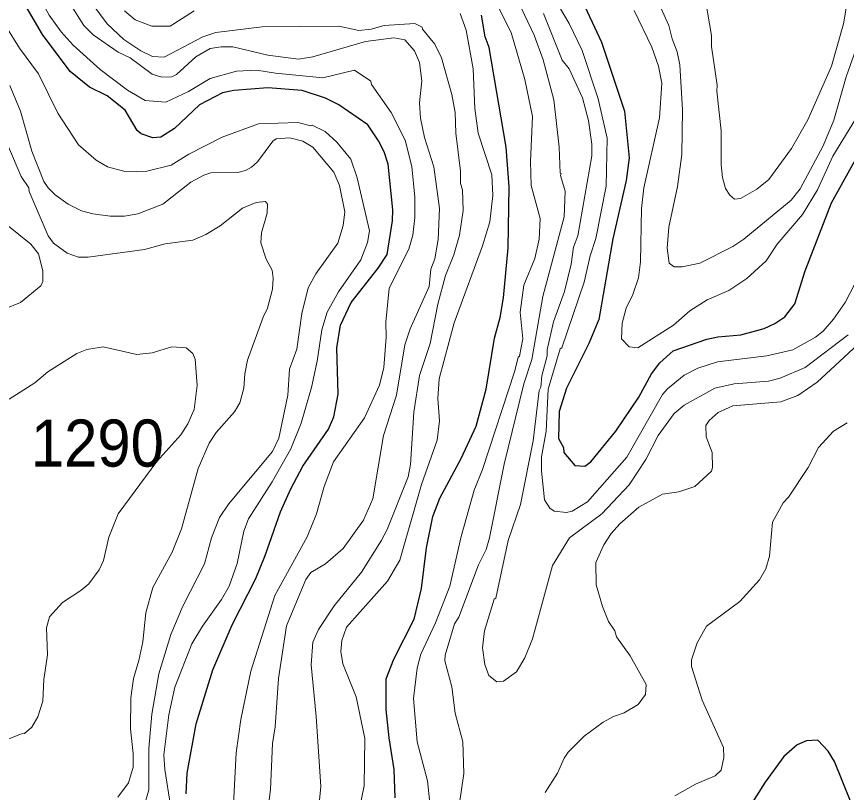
# Model space of a CAD drawing. Extents: x 598.3 to 623.2, y 6902.2 to 6930.1.
# Drawn here: x 605.43 to 606.84, y 6922.266 to 6923.585 of the extents above; entities that cross this region are included whole.
import ezdxf

# ---------------------------------------------------------------- set-up
doc = ezdxf.new("R2010")
doc.units = 0
doc.header["$LTSCALE"] = 0.032
doc.layers.add('1', color=7, linetype='Continuous', lineweight=25)
doc.layers.add('2', color=7, linetype='Continuous', lineweight=13)
doc.layers.add('21', color=7, linetype='Continuous')

msp = doc.modelspace()

# ---------------------------------------------------------------- linework, layer by layer
at = {"layer": '1'}
for points in [[(606.3883, 6923.6191), (606.4241, 6923.541), (606.4632, 6923.4239), (606.4712, 6923.3445), (606.4663, 6923.306), (606.4437, 6923.2072), (606.4195, 6923.0699), (606.4026, 6923.0294), (606.3646, 6922.9533), (606.3522, 6922.9139), (606.3514, 6922.8675), (606.3595, 6922.8526), (606.3604, 6922.8439), (606.379, 6922.8221), (606.3957, 6922.8207), (606.4062, 6922.8283), (606.4485, 6922.8802), (606.4878, 6922.9379), (606.5094, 6922.9776), (606.5237, 6922.9965), (606.5463, 6923.0169), (606.6031, 6923.0366), (606.6221, 6923.0405), (606.6609, 6923.0438), (606.7008, 6923.0549), (606.7187, 6923.063), (606.7358, 6923.0745), (606.7529, 6923.0964), (606.7702, 6923.1529), (606.8149, 6923.2681), (606.8912, 6923.4045)], [(605.7184, 6922.264), (605.72, 6922.299), (605.7354, 6922.3827), (605.764, 6922.4745), (605.7966, 6922.5509), (605.8369, 6922.6299), (605.853, 6922.6688), (605.879, 6922.7429), (605.8962, 6922.7824), (605.9167, 6922.8207), (605.9604, 6922.8836), (605.9694, 6922.9048), (605.9766, 6922.943), (605.9743, 6923.0217), (605.9807, 6923.0602), (605.9987, 6923.099), (606.0446, 6923.157), (606.06, 6923.1805), (606.0689, 6923.2377), (606.0697, 6923.2561), (606.0618, 6923.3338), (606.055, 6923.3548), (606.0456, 6923.3738), (606.0274, 6923.4008), (605.9777, 6923.4345), (605.9551, 6923.4459), (605.9159, 6923.4589), (605.8573, 6923.4638), (605.7996, 6923.459), (605.7802, 6923.455), (605.7414, 6923.4349), (605.6987, 6923.3947), (605.6752, 6923.3799), (605.6617, 6923.3789), (605.6422, 6923.3855), (605.6353, 6923.3909), (605.6148, 6923.4258), (605.5843, 6923.45), (605.5543, 6923.465), (605.5211, 6923.4911), (605.4746, 6923.5542), (605.4373, 6923.6175)], [(606.0738, 6922.257), (606.0722, 6922.3051), (606.0632, 6922.3592), (606.0585, 6922.4071), (606.0585, 6922.4592), (606.0712, 6922.493), (606.1057, 6922.5609), (606.1183, 6922.6127), (606.1268, 6922.6817), (606.1377, 6922.7352), (606.1497, 6922.7666), (606.1857, 6922.8335), (606.2112, 6922.8888), (606.2285, 6922.9517), (606.2425, 6923.0383), (606.2519, 6923.0731), (606.2575, 6923.1065), (606.2656, 6923.192), (606.2672, 6923.2953), (606.2623, 6923.3629), (606.2333, 6923.5323), (606.2268, 6923.5501), (606.2201, 6923.5868)], [(606.8614, 6922.2164), (606.82, 6922.3187), (606.8096, 6922.3362), (606.7922, 6922.3553), (606.7724, 6922.354), (606.7569, 6922.347), (606.7342, 6922.3272), (606.7027, 6922.2837), (606.6772, 6922.2433)]]:
    msp.add_lwpolyline(points, dxfattribs=at)
at = {"layer": '2'}
for points in [[(605.4267, 6923.7275), (605.4576, 6923.6398), (605.4858, 6923.5868), (605.5059, 6923.559), (605.5263, 6923.536), (605.5725, 6923.4947), (605.6186, 6923.4595), (605.6488, 6923.4421), (605.6842, 6923.4395), (605.7222, 6923.4576), (605.7591, 6923.4793)], [(606.5969, 6923.6357), (606.6112, 6923.5524), (606.6114, 6923.5339), (606.6209, 6923.4679), (606.6202, 6923.458), (606.6274, 6923.3908), (606.6274, 6923.3326)], [(605.8504, 6922.1827), (605.8618, 6922.2713), (605.8653, 6922.3497), (605.8697, 6922.3778), (605.8753, 6922.46), (605.8891, 6922.5494), (605.922, 6922.6279), (605.9306, 6922.6398), (605.9552, 6922.6548), (605.9852, 6922.6806), (606.02, 6922.7289), (606.0357, 6922.7653), (606.0541, 6922.8728), (606.0761, 6922.9412), (606.0901, 6923.0269), (606.0992, 6923.0543), (606.1312, 6923.1263), (606.1345, 6923.1554), (606.1409, 6923.1733), (606.1467, 6923.2059), (606.1491, 6923.2586), (606.1396, 6923.3294), (606.1238, 6923.3794), (606.1167, 6923.4123), (606.1151, 6923.4381), (606.1192, 6923.4756), (606.115, 6923.5067), (606.1068, 6923.5263), (606.0902, 6923.5449), (606.0713, 6923.5488), (606.0231, 6923.5424), (605.934, 6923.5165), (605.9094, 6923.5125), (605.8575, 6923.5193), (605.7977, 6923.5334), (605.7778, 6923.5334), (605.7592, 6923.5303), (605.7347, 6923.5164), (605.702, 6923.4863), (605.6939, 6923.4824), (605.6774, 6923.4817), (605.6607, 6923.487), (605.6232, 6923.5147), (605.6031, 6923.5242), (605.5603, 6923.5538), (605.5446, 6923.5696), (605.5133, 6923.6191)], [(605.5466, 6923.6236), (605.584, 6923.5723), (605.6128, 6923.546), (605.6414, 6923.5267), (605.6612, 6923.5167), (605.6809, 6923.5156), (605.747, 6923.5502), (605.7687, 6923.5577), (605.8477, 6923.5674), (605.9779, 6923.5682), (606.012, 6923.561), (606.0328, 6923.5634), (606.0552, 6923.5698), (606.1069, 6923.5731), (606.1198, 6923.5666), (606.1201, 6923.5634), (606.1408, 6923.5378), (606.1523, 6923.5146), (606.1701, 6923.452), (606.1757, 6923.4215), (606.1766, 6923.3863), (606.1846, 6923.3222), (606.1847, 6923.3012), (606.1879, 6923.2903), (606.1895, 6923.2552), (606.1829, 6923.2132), (606.1734, 6923.18), (606.1592, 6923.1447), (606.1459, 6923.0958), (606.1329, 6923.0294), (606.1148, 6922.9748), (606.1053, 6922.9123), (606.0997, 6922.8238), (606.0957, 6922.8028), (606.0598, 6922.7129), (606.0501, 6922.6938), (606.0165, 6922.6409), (605.97, 6922.5834), (605.9433, 6922.5432), (605.934, 6922.5214), (605.9307, 6922.4831), (605.9395, 6922.3955), (605.9475, 6922.2766), (605.9426, 6922.2308)], [(606.1903, 6922.2985), (606.1887, 6922.3524), (606.1758, 6922.4008), (606.1702, 6922.4458), (606.158, 6922.4898), (606.1587, 6922.4995), (606.1747, 6922.5526), (606.1818, 6922.5639), (606.2152, 6922.653), (606.2283, 6922.6794), (606.2341, 6922.6992), (606.2589, 6922.8242), (606.2925, 6922.9605), (606.3061, 6923.0019), (606.3248, 6923.1088), (606.3611, 6923.2445), (606.3627, 6923.2881), (606.3548, 6923.3144), (606.356, 6923.318), (606.3539, 6923.3185), (606.3524, 6923.3628), (606.3434, 6923.4431), (606.3249, 6923.5111), (606.3097, 6923.5529), (606.2784, 6923.6203)], [(606.5577, 6923.5025), (606.553, 6923.5245), (606.5442, 6923.5466), (606.5385, 6923.5696), (606.5116, 6923.6301)], [(606.6274, 6923.3326), (606.6298, 6923.3111), (606.6349, 6923.2928), (606.6424, 6923.2813), (606.6505, 6923.2745), (606.6606, 6923.2753), (606.6884, 6923.2916), (606.7086, 6923.3078), (606.7471, 6923.3608), (606.7747, 6923.4094), (606.8153, 6923.5005), (606.8354, 6923.5726), (606.8436, 6923.62)], [(606.2415, 6923.6166), (606.271, 6923.5575), (606.2939, 6923.4776), (606.3069, 6923.415), (606.3036, 6923.3383), (606.3045, 6923.2977), (606.3198, 6923.2415), (606.3182, 6923.2066), (606.3111, 6923.1738), (606.2925, 6923.1285), (606.2859, 6923.0823), (606.2907, 6923.037), (606.285, 6923.0077), (606.2825, 6923.0061), (606.2771, 6922.9828), (606.2223, 6922.8148), (606.2081, 6922.7798), (606.1856, 6922.7015), (606.1665, 6922.6169), (606.1424, 6922.5546), (606.1173, 6922.5014), (606.1111, 6922.4777), (606.1046, 6922.4262), (606.111, 6922.3524), (606.1288, 6922.2863), (606.1344, 6922.2321)], [(606.3337, 6922.9513), (606.3538, 6923.02), (606.3571, 6923.0216), (606.3948, 6923.1334), (606.4049, 6923.1784), (606.4146, 6923.2075), (606.4323, 6923.2963), (606.4339, 6923.3778), (606.4187, 6923.445), (606.3915, 6923.5268), (606.3694, 6923.5729), (606.3456, 6923.6138)], [(605.7323, 6923.5946), (605.6915, 6923.5685), (605.6604, 6923.5682), (605.6317, 6923.579), (605.6135, 6923.5945)], [(606.48, 6923.5952), (606.5099, 6923.5329), (606.5214, 6923.5005), (606.527, 6923.4714), (606.523, 6923.4128), (606.4962, 6923.2937), (606.4923, 6923.2583), (606.4906, 6923.1679), (606.4869, 6923.1407), (606.4774, 6923.1125), (606.4664, 6923.0893), (606.4597, 6923.0638), (606.4581, 6923.0369), (606.4714, 6923.0235), (606.4858, 6923.0219), (606.5469, 6923.0603), (606.5746, 6923.0847), (606.6038, 6923.1035), (606.6405, 6923.1194), (606.6714, 6923.1397), (606.7039, 6923.1696), (606.7231, 6923.1977), (606.7659, 6923.2486), (606.7912, 6923.2904), (606.8174, 6923.3476), (606.862, 6923.4204)], [(606.0064, 6922.2061), (606.0211, 6922.2777), (606.0219, 6922.3578), (606.0074, 6922.4288), (605.9848, 6922.4849), (605.9816, 6922.5057), (605.9829, 6922.5247), (605.9907, 6922.5472), (606.0604, 6922.6255), (606.0814, 6922.661), (606.1183, 6922.7898), (606.1449, 6922.8651), (606.149, 6922.8975), (606.1459, 6922.9359), (606.1482, 6922.969), (606.1741, 6923.0645), (606.2223, 6923.1953), (606.2347, 6923.2358), (606.2397, 6923.2806), (606.2381, 6923.316), (606.2147, 6923.3864), (606.2091, 6923.4285), (606.2065, 6923.4957), (606.1944, 6923.5616), (606.1839, 6923.5899)], [(606.3259, 6923.59), (606.3574, 6923.5108), (606.3691, 6923.4957), (606.392, 6923.4466), (606.4024, 6923.408), (606.408, 6923.3678), (606.408, 6923.3479), (606.3839, 6923.2124), (606.3766, 6923.1929), (606.3725, 6923.1638), (606.3617, 6923.1173), (606.3425, 6923.0662), (606.3322, 6923.0184), (606.332, 6923.0081), (606.3231, 6922.9744), (606.3214, 6922.9549), (606.3182, 6922.9495), (606.308, 6922.8639), (606.2867, 6922.7558), (606.2657, 6922.6943), (606.2447, 6922.5967), (606.242, 6922.5945), (606.2257, 6922.5409), (606.222, 6922.5118), (606.2259, 6922.4835), (606.2331, 6922.4652), (606.2463, 6922.4545), (606.2577, 6922.4553), (606.2799, 6922.4714), (606.2939, 6922.4949), (606.307, 6922.5275), (606.341, 6922.6521), (606.37, 6922.6988), (606.4251, 6922.7398), (606.4716, 6922.7888), (606.4998, 6922.8322)], [(605.6821, 6922.3054), (605.6804, 6922.3303), (605.689, 6922.3984), (605.699, 6922.445), (605.7281, 6922.519), (605.7463, 6922.5489), (605.7785, 6922.5939), (605.7915, 6922.6169), (605.8051, 6922.6554), (605.8164, 6922.7105), (605.8244, 6922.7313), (605.8649, 6922.7944), (605.8961, 6922.8504), (605.914, 6922.8937), (605.9313, 6922.9544), (605.9409, 6922.9994), (605.9489, 6923.0525), (605.9579, 6923.0823), (605.9776, 6923.1168), (606.0154, 6923.1714), (606.0269, 6923.201), (606.0299, 6923.2208), (606.009, 6923.3108), (605.9981, 6923.3422), (605.9746, 6923.3712), (605.9547, 6923.3893), (605.9324, 6923.4004), (605.9301, 6923.3992), (605.9084, 6923.4047), (605.8415, 6923.4023), (605.7799, 6923.3796), (605.7228, 6923.351), (605.6931, 6923.3321), (605.6517, 6923.3221), (605.6163, 6923.3207), (605.5846, 6923.3292), (605.5656, 6923.3409), (605.5357, 6923.3665), (605.5002, 6923.4208), (605.4675, 6923.4875), (605.4352, 6923.5308), (605.4119, 6923.5686)], [(606.86, 6923.5381), (606.8403, 6923.4824), (606.819, 6923.4086), (606.8012, 6923.3653), (606.762, 6923.292), (606.7466, 6923.2729), (606.6664, 6923.2062), (606.6475, 6923.1941), (606.5916, 6923.1654), (606.5612, 6923.1597), (606.5477, 6923.1595), (606.5391, 6923.1656), (606.5361, 6923.1911), (606.5389, 6923.2266), (606.5532, 6923.2957), (606.561, 6923.3502), (606.5619, 6923.4265), (606.5577, 6923.5025)], [(605.7591, 6923.4793), (605.804, 6923.4921), (605.8385, 6923.4937), (605.8705, 6923.4883), (605.9509, 6923.4808), (606.0043, 6923.4936), (606.0324, 6923.475), (606.0334, 6923.4695), (606.0666, 6923.4215), (606.0905, 6923.3746), (606.1022, 6923.3298), (606.1069, 6923.2779), (606.1069, 6923.2433), (606.1039, 6923.2132), (606.0971, 6923.1892), (606.0633, 6923.123), (606.0577, 6923.0652), (606.0583, 6923.04), (606.0545, 6922.9885), (606.0472, 6922.9585), (606.0213, 6922.9031), (605.9691, 6922.8279), (605.9531, 6922.7863), (605.9399, 6922.7399), (605.9239, 6922.7004), (605.8692, 6922.6007), (605.8284, 6922.4722), (605.8116, 6922.3902), (605.8035, 6922.3336), (605.7977, 6922.2243)], [(605.6466, 6922.2413), (605.6552, 6922.2708), (605.6553, 6922.3411), (605.6601, 6922.3994), (605.6723, 6922.4676), (605.6925, 6922.5348), (605.713, 6922.5829), (605.7497, 6922.6546), (605.7613, 6922.6989), (605.7753, 6922.7335), (605.7903, 6922.7564), (605.8653, 6922.8457), (605.876, 6922.8682), (605.891, 6922.9412), (605.8941, 6922.9857), (605.9063, 6923.0197), (605.9152, 6923.0799), (605.9261, 6923.1236), (605.9386, 6923.1473), (605.9761, 6923.1997), (605.9855, 6923.2297), (605.9879, 6923.2531), (605.9791, 6923.2977), (605.9695, 6923.3203), (605.9335, 6923.3628), (605.9167, 6923.3727), (605.8944, 6923.3789), (605.8717, 6923.3772), (605.8656, 6923.373), (605.8396, 6923.3381), (605.8294, 6923.3287), (605.8191, 6923.323), (605.8064, 6923.3198), (605.7605, 6923.3189), (605.7486, 6923.3154), (605.7265, 6923.3035), (605.679, 6923.266), (605.6361, 6923.2494), (605.6138, 6923.2453), (605.5895, 6923.2454), (605.56, 6923.2493), (605.5406, 6923.2548), (605.5182, 6923.266), (605.4958, 6923.282), (605.4838, 6923.2936), (605.4766, 6923.3043), (605.4561, 6923.3562), (605.4368, 6923.424), (605.4191, 6923.4674)], [(605.4165, 6923.3632), (605.4382, 6923.3127), (605.4509, 6923.2936), (605.4515, 6923.2875), (605.4838, 6923.2119), (605.493, 6923.1996), (605.5163, 6923.1828), (605.5355, 6923.1757), (605.5522, 6923.1757), (605.6476, 6923.1887), (605.6831, 6923.1984), (605.7297, 6923.2048), (605.7521, 6923.2143)], [(605.7521, 6923.2143), (605.7765, 6923.2289), (605.8145, 6923.2589), (605.8377, 6923.2686), (605.8535, 6923.2702), (605.8568, 6923.266), (605.856, 6923.2507), (605.8464, 6923.2172), (605.8456, 6923.2002), (605.8542, 6923.1722), (605.8649, 6923.1539), (605.8666, 6923.1403), (605.865, 6923.1217), (605.8569, 6923.0893), (605.8491, 6923.0737), (605.823, 6923.001), (605.818, 6922.9779), (605.8163, 6922.953), (605.8096, 6922.9282), (605.8007, 6922.9133), (605.7695, 6922.8777), (605.7575, 6922.8597), (605.7388, 6922.8167), (605.7108, 6922.7142), (605.6949, 6922.6746), (605.6621, 6922.6148), (605.6497, 6922.5713), (605.6447, 6922.5222), (605.6383, 6922.4903), (605.6291, 6922.46), (605.6245, 6922.4269), (605.6238, 6922.3742), (605.6285, 6922.3319), (605.6286, 6922.3091), (605.6204, 6922.2828), (605.6024, 6922.2583)], [(605.4095, 6923.0875), (605.4367, 6923.0989), (605.4714, 6923.127), (605.4747, 6923.1344), (605.4747, 6923.1525), (605.4673, 6923.1816), (605.4546, 6923.198), (605.3693, 6923.2657)], [(606.8543, 6923.1296), (606.8385, 6923.0988), (606.8186, 6923.0703), (606.8009, 6923.0504), (606.7877, 6923.0399), (606.7495, 6923.0185), (606.705, 6923.0081), (606.6216, 6922.9983), (606.5878, 6922.987), (606.5646, 6922.9753), (606.5363, 6922.9524), (606.528, 6922.9425), (606.4675, 6922.836), (606.4006, 6922.7603), (606.3747, 6922.7444), (606.3647, 6922.7418), (606.3439, 6922.7444), (606.3365, 6922.7495), (606.3272, 6922.7638), (606.3223, 6922.8129), (606.3224, 6922.8365), (606.3303, 6922.88), (606.3337, 6922.9513)], [(606.8906, 6923.056), (606.7908, 6922.9634), (606.7578, 6922.9408), (606.7288, 6922.93), (606.6475, 6922.9231), (606.6226, 6922.9119), (606.6071, 6922.8985), (606.6016, 6922.8896), (606.6024, 6922.8703), (606.6121, 6922.8441), (606.613, 6922.8185), (606.6111, 6922.8121), (606.5831, 6922.7863), (606.5557, 6922.7774), (606.5282, 6922.7734), (606.4879, 6922.7509), (606.4552, 6922.7225), (606.4406, 6922.7063), (606.428, 6922.6868), (606.4147, 6922.6568), (606.4154, 6922.6193), (606.426, 6922.5821), (606.4362, 6922.5568), (606.4468, 6922.541), (606.4496, 6922.531), (606.473, 6922.4987), (606.5003, 6922.4495), (606.4992, 6922.4327), (606.4865, 6922.4155), (606.4626, 6922.4015), (606.4448, 6922.3951), (606.4273, 6922.3855), (606.3949, 6922.362), (606.3678, 6922.3348), (606.361, 6922.3247), (606.3497, 6922.2988), (606.3284, 6922.2661)], [(606.4998, 6922.8322), (606.5204, 6922.873), (606.5477, 6922.9104), (606.5649, 6922.9246), (606.6169, 6922.953), (606.6496, 6922.9604), (606.7079, 6922.9652), (606.728, 6922.9704), (606.7705, 6922.9885), (606.8432, 6923.0441)], [(605.4177, 6922.9347), (605.4614, 6922.9626), (605.4834, 6922.9812), (605.5328, 6923.012), (605.5495, 6923.0192), (605.5775, 6923.0234), (605.6345, 6923.0106), (605.6608, 6923.0135), (605.6939, 6923.0234), (605.7183, 6923.0217), (605.73, 6923.0123), (605.7338, 6923.0027), (605.7371, 6922.958), (605.7323, 6922.9171), (605.7215, 6922.8929), (605.7097, 6922.874), (605.6688, 6922.8289), (605.6027, 6922.7399), (605.5872, 6922.7003), (605.5779, 6922.6604), (605.5704, 6922.6448), (605.553, 6922.621), (605.5397, 6922.6092), (605.5083, 6922.589), (605.4862, 6922.5647), (605.4813, 6922.5458), (605.4828, 6922.5001), (605.4764, 6922.4585), (605.4749, 6922.4216), (605.4667, 6922.3948), (605.4561, 6922.377), (605.4436, 6922.3665), (605.4384, 6922.3661), (605.4113, 6922.3549)], [(606.5487, 6922.2608), (606.5843, 6922.2802), (606.6177, 6922.2946), (606.6274, 6922.3042), (606.6323, 6922.3259), (606.6315, 6922.3426), (606.5953, 6922.423), (606.5773, 6922.4801), (606.5773, 6922.4916), (606.5868, 6922.5206), (606.6029, 6922.5487), (606.6595, 6922.5908), (606.693, 6922.6276), (606.7033, 6922.6465), (606.7099, 6922.6676), (606.7151, 6922.7254), (606.7332, 6922.7583), (606.7422, 6922.7683), (606.7755, 6922.8185), (606.7933, 6922.8524), (606.8188, 6922.8804), (606.8418, 6922.8946)], [(605.6917, 6922.2442), (605.6821, 6922.3054)], [(606.1818, 6922.2403), (606.1903, 6922.2985)]]:
    msp.add_lwpolyline(points, dxfattribs=at)

# ---------------------------------------------------------------- texts
at = {"layer": '21', "width": 0.95}
msp.add_text('1290', height=0.08, dxfattribs=at).set_placement((605.4546, 6922.82))

doc.saveas('drawing.dxf')
